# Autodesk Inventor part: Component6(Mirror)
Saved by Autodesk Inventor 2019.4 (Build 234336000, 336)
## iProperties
Created: 2020-06
Part Number: Component6(Mirror)
Material: Generic
Document SubType Name: Modeling
Designer: Administrator
Density: 1 g/cm^3
Appearance: Default
Title: Component6(Mirror)
Author: Administrator
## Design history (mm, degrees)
